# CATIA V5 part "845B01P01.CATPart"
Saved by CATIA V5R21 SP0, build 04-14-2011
Part number: 845B01P21
Bounding box of the stored display mesh (mm): x -76.5 to 76.5, y -25.54 to 25.54, z -6.5 to 6.5
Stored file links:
  C:\Users\ALI OZGUN\Desktop\alhan\845B01P01.CATPart
  Copy (1) of 845B01P21.CATPart
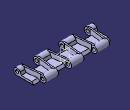
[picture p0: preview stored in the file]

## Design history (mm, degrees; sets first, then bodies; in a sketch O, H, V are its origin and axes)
Body1 (main body)
  Sketch1 on yz-plane, origin (0, 0, 0), H (0, 1, 0), V (0, 0, 1)
    construction line L1 (-19.05, 0) -> (19.05, 0)
    point P1 (-19.05, 0)
    point P2 (19.05, 0)
    line L2 (-19.05, 6.5) -> (19.05, 6.5)
    line L3 (19.05, -6.5) -> (-19.05, -6.5)
    arc A1 centre (19.05, 0) radius 6.5 from (19.05, 6.5) to (19.05, -6.5) cw
    arc A2 centre (-19.05, 0) radius 6.5 from (-19.05, -6.5) to (-19.05, 6.5) cw
    circle A3 centre (19.05, 0) radius 3.25
    circle A4 centre (-19.05, 0) radius 3.25
    distance L1 L2 = 6.5
    length L1 = 38.1
    distance P2 V = 19.05
    radius A3 = 3.25
    radius A4 = 3.25
    coincidence: P1 H
    horizontal: L1 H
    tangency: A1 L2, A2 L2, A1 L3, A2 L3
  Pad1: profile Sketch1, direction (1, 0, 0), length 76.5, mirrored extent
  Sketch2 on face of Pad1 from Sketch1.L2, origin (0, 0, 6.5), H (1, 0, 0), V (0, 1, 0)
    line L1 (38, -14) -> (64, -14)
    line L2 (64, -14) -> (64, -36.0786)
    line L3 (64, -36.0786) -> (38, -36.0786)
    line L4 (38, -36.0786) -> (38, -14)
    line L5 (-13, -14) -> (13, -14)
    line L6 (13, -14) -> (13, -36.0786)
    line L7 (13, -36.0786) -> (-13, -36.0786)
    line L8 (-13, -36.0786) -> (-13, -14)
    point P7 (13, -36.0786)
    line L9 (-64, -14) -> (-38, -14)
    line L10 (-38, -14) -> (-38, -32.269)
    line L11 (-38, -32.269) -> (-64, -32.269)
    line L12 (-64, -32.269) -> (-64, -14)
    line L13 (85.7823, 31.3847) -> (63.5, 31.3847)
    line L14 (63.5, 31.3847) -> (63.5, 14)
    line L15 (63.5, 14) -> (85.7823, 14)
    line L16 (85.7823, 14) -> (85.7823, 31.3847)
    point P17 (12.5, 31.3847)
    line L17 (12.5, 31.3847) -> (38.5, 31.3847)
    line L18 (38.5, 31.3847) -> (38.5, 14)
    line L19 (38.5, 14) -> (12.5, 14)
    line L20 (12.5, 14) -> (12.5, 31.3847)
    point P19 (38.5, 14)
    line L21 (-38.5, 32.0801) -> (-12.5, 32.0801)
    line L22 (-12.5, 32.0801) -> (-12.5, 14)
    line L23 (-12.5, 14) -> (-38.5, 14)
    line L24 (-38.5, 14) -> (-38.5, 32.0801)
    point P23 (-12.5, 14)
    line L25 (-81.4786, 33.8185) -> (-63.5, 33.8185)
    line L26 (-63.5, 33.8185) -> (-63.5, 14)
    line L27 (-63.5, 14) -> (-81.4786, 14)
    line L28 (-81.4786, 14) -> (-81.4786, 33.8185)
    point P27 (-63.5, 14)
    reference projected line E1 (76.5, 19.05) -> (76.5, -19.05) from edge [face of Pad1 from Sketch1.L2 | end face of Pad1]
    reference projected line E2 (-76.5, 19.05) -> (-76.5, -19.05) from edge [start face of Pad1 | face of Pad1 from Sketch1.L2]
    reference projected line E3 (-76.5, 19.05) -> (-76.5, -19.05) from edge [start face of Pad1 | face of Pad1 from Sketch1.L2]
    reference projected line E4 (76.5, 19.05) -> (76.5, -19.05) from edge [face of Pad1 from Sketch1.L2 | end face of Pad1]
    distance L14 E1 = 13
    distance L26 E2 = 13
    distance L12 E3 = 12.5
    distance L2 E4 = 12.5
    distance L23 L5 = 28
    distance L5 H = 14
    distance L4 L2 = 26
    distance L12 L10 = 26
    distance L10 L8 = 25
    distance L6 L4 = 25
    distance L24 L26 = 25
    distance L18 L14 = 25
    distance L26 L22 = 51
    distance L20 L18 = 26
    horizontal: L1 H, L3 H, L5 H, L7 H, L9 H, L11 H, L13 H, L15 H, L17 H, L19 H, L21 H, L23 H, L25 H, L27 H
    vertical: L2 V, L4 V, L6 V, L8 V, L10 V, L12 V, L14 V, L16 V, L18 V, L20 V, L22 V, L24 V, L26 V, L28 V
    coincidence: P7 L3, P17 L13, P19 L15, P23 L15, P27 L15, L1 L5, L9 L5
  Pocket1: profile Sketch2, direction (0, 0, -1), length 53.5
  Sketch3 on end face of Pad1, origin (76.5, 0, 0), H (0, 1, 0), V (0, 0, 1)
    projected arc E1 centre (19.05, 0) radius 6.5 from (19.05, -6.5) to (19.05, 6.5) ccw from edge [face of Pocket1 from Sketch2.L14 | face of Pad1 from Sketch1.A1]
    projected arc E2 centre (19.05, 0) radius 6.5 from (19.05, -6.5) to (13.0358, 2.4657) ccw from edge [face of Pocket1 from Sketch2.L14 | face of Pad1 from Sketch1.A1]
    point P1 (19.05, -6.5)
    projected arc E3 centre (-19.05, 0) radius 6.5 from (-19.05, 6.5) to (-19.05, -6.5) ccw from edge [face of Pad1 from Sketch1.A2 | end face of Pad1]
    projected arc E4 centre (-19.05, 0) radius 6.5 from (-13.0358, 2.4657) to (-19.05, -6.5) ccw from edge [face of Pad1 from Sketch1.A2 | end face of Pad1]
    point P4 (-19.05, -6.5)
    projected line E5 (-19.05, -6.5) -> (14, -6.5) from edge [face of Pad1 from Sketch1.L3 | end face of Pad1]
    point P5 (-19.05, -6.5)
    projected line E6 (19.05, -6.5) -> (14, -6.5) from edge [face of Pocket1 from Sketch2.L14 | face of Pad1 from Sketch1.L3]
    point P7 (19.05, -6.5)
    line L1 (-13.0358, 2.4657) -> (-11, -2.5)
    line L2 (-11, -2.5) -> (11, -2.5)
    point P10 (11, -2.5)
    line L3 (11, -2.5) -> (13.0358, 2.4657)
    distance L2 E5 = 4
    length L2 = 22
    distance P10 V = 11
    horizontal: L2 H
    tangency: L3 E1, L1 E3
    coincidence: P1 P7, P4 P5
  Pocket2: profile Sketch3, direction (-1, 0, 0), length 172.5, outer side
  Sketch4 on face of Pocket2 from Sketch3.L2, origin (0, 0, -2.5), H (1, 0, 0), V (0, 1, 0)
    projected line E1 (38, -14) -> (38, -25.55) from edge [face of Pocket2 | face of Pocket1 from Sketch2.L4]
    projected line E2 (38, -14) -> (38, -19.05) from edge [face of Pocket2 | face of Pocket1 from Sketch2.L4]
    point P1 (38, -14)
    point P2 (38, -25.55)
    projected line E3 (13, -25.55) -> (13, -14) from edge [face of Pocket2 | face of Pocket1 from Sketch2.L6]
    projected line E4 (13, -19.05) -> (13, -14) from edge [face of Pocket2 | face of Pocket1 from Sketch2.L6]
    point P3 (13, -25.55)
    point P4 (13, -14)
    projected line E5 (64, -25.55) -> (64, -14) from edge [face of Pocket2 | face of Pocket1 from Sketch2.L2]
    projected line E6 (64, -19.05) -> (64, -14) from edge [face of Pocket2 | face of Pocket1 from Sketch2.L2]
    point P5 (64, -25.55)
    point P6 (64, -14)
    projected line E7 (38.5, 14) -> (38.5, 25.55) from edge [face of Pocket2 | face of Pocket1 from Sketch2.L18]
    projected line E8 (38.5, 14) -> (38.5, 19.05) from edge [face of Pocket2 | face of Pocket1 from Sketch2.L18]
    point P7 (38.5, 14)
    point P8 (38.5, 25.55)
    projected line E9 (63.5, 14) -> (63.5, 25.55) from edge [face of Pocket1 from Sketch2.L14 | face of Pocket2]
    projected line E10 (63.5, 14) -> (63.5, 19.05) from edge [face of Pocket1 from Sketch2.L14 | face of Pocket2]
    point P9 (63.5, 14)
    point P10 (63.5, 25.55)
    projected line E11 (12.5, 25.55) -> (12.5, 14) from edge [face of Pocket2 | face of Pocket1 from Sketch2.L20]
    projected line E12 (12.5, 19.05) -> (12.5, 14) from edge [face of Pocket2 | face of Pocket1 from Sketch2.L20]
    point P11 (12.5, 25.55)
    point P12 (12.5, 14)
    offset line E13 (9.5, 25.55) -> (9.5, 14) from edge [face of Pocket2 | face of Pocket1 from Sketch2.L20]
    offset line E14 (9.5, 19.05) -> (9.5, 14) from edge [face of Pocket2 | face of Pocket1 from Sketch2.L20]
    point P13 (9.5, 25.55)
    point P14 (9.5, 14)
    offset line E15 (16, -25.55) -> (16, -14) from edge [face of Pocket2 | face of Pocket1 from Sketch2.L6]
    offset line E16 (16, -19.05) -> (16, -14) from edge [face of Pocket2 | face of Pocket1 from Sketch2.L6]
    point P15 (16, -25.55)
    point P16 (16, -14)
    offset line E17 (35, -14) -> (35, -25.55) from edge [face of Pocket2 | face of Pocket1 from Sketch2.L4]
    offset line E18 (35, -14) -> (35, -19.05) from edge [face of Pocket2 | face of Pocket1 from Sketch2.L4]
    point P17 (35, -14)
    point P18 (35, -25.55)
    offset line E19 (41.5, 14) -> (41.5, 25.55) from edge [face of Pocket2 | face of Pocket1 from Sketch2.L18]
    offset line E20 (41.5, 14) -> (41.5, 19.05) from edge [face of Pocket2 | face of Pocket1 from Sketch2.L18]
    point P19 (41.5, 14)
    point P20 (41.5, 25.55)
    offset line E21 (60.5, 14) -> (60.5, 25.55) from edge [face of Pocket1 from Sketch2.L14 | face of Pocket2]
    offset line E22 (60.5, 14) -> (60.5, 19.05) from edge [face of Pocket1 from Sketch2.L14 | face of Pocket2]
    point P21 (60.5, 14)
    point P22 (60.5, 25.55)
    offset line E23 (67, -25.55) -> (67, -14) from edge [face of Pocket2 | face of Pocket1 from Sketch2.L2]
    offset line E24 (67, -19.05) -> (67, -14) from edge [face of Pocket2 | face of Pocket1 from Sketch2.L2]
    point P23 (67, -25.55)
    point P24 (67, -14)
    line L1 (13, -14) -> (9.5, 14)
    line L2 (16, -14) -> (12.5, 14)
    line L3 (35, -14) -> (38.5, 14)
    line L4 (38, -14) -> (41.5, 14)
    line L5 (64, -14) -> (60.5, 14)
    line L6 (67, -14) -> (63.5, 14)
    projected line E25 through (0, -19.05) direction (1, 0) from axis of face of Pocket2
    projected line E26 (13, -19.05) -> (16, -19.05) from axis of face of Pocket2
    projected line E27 (64, -19.05) -> (67, -19.05) from axis of face of Pocket2
    projected line E28 (35, -19.05) -> (38, -19.05) from axis of face of Pocket2
    point P25 (-10000000, -19.05)
    point P26 (10000000, -19.05)
    point P27 (67, -19.05)
    point P28 (38, -19.05)
    point P29 (64, -19.05)
    point P30 (64, -19.05)
    point P31 (38, -19.05)
    point P32 (35, -19.05)
    point P33 (16, -19.05)
    point P34 (35, -19.05)
    point P35 (16, -19.05)
    point P36 (13, -19.05)
    point P37 (13, -19.05)
    projected line E29 through (0, 19.05) direction (1, 0) from axis of face of Pocket2
    projected line E30 (9.5, 19.05) -> (12.5, 19.05) from axis of face of Pocket2
    projected line E31 (38.5, 19.05) -> (41.5, 19.05) from axis of face of Pocket2
    projected line E32 (60.5, 19.05) -> (63.5, 19.05) from axis of face of Pocket2
    point P38 (-10000000, 19.05)
    point P39 (10000000, 19.05)
    point P40 (63.5, 19.05)
    point P41 (9.5, 19.05)
    point P42 (9.5, 19.05)
    point P43 (12.5, 19.05)
    point P44 (12.5, 19.05)
    point P45 (38.5, 19.05)
    point P46 (38.5, 19.05)
    point P47 (41.5, 19.05)
    point P48 (60.5, 19.05)
    point P49 (41.5, 19.05)
    point P50 (60.5, 19.05)
    point P51 (-10000000, -19.05)
    point P52 (10000000, -19.05)
    point P53 (-10000000, 19.05)
    point P54 (10000000, 19.05)
    construction line L7 through (0, -19.05) direction (-1, 0)
    construction line L8 through (0, 19.05) direction (-1, 0)
    point P55 (-10000000, -19.05)
    point P56 (10000000, -19.05)
    point P57 (-16, -19.05)
    point P58 (-13, -19.05)
    point P59 (-67, -19.05)
    point P60 (-64, -19.05)
    point P61 (-38, -19.05)
    point P62 (-35, -19.05)
    point P63 (-38, -25.55)
    point P64 (-38, -14)
    point P65 (-38, -19.05)
    point P66 (-13, -14)
    point P67 (-13, -25.55)
    point P68 (-13, -19.05)
    point P69 (-64, -14)
    point P70 (-64, -25.55)
    point P71 (-64, -19.05)
    point P72 (-38.5, 25.55)
    point P73 (-38.5, 14)
    point P74 (-38.5, 19.05)
    point P75 (-63.5, 25.55)
    point P76 (-63.5, 14)
    point P77 (-63.5, 19.05)
    point P78 (-12.5, 14)
    point P79 (-12.5, 25.55)
    point P80 (-12.5, 19.05)
    point P81 (-9.5, 14)
    point P82 (-9.5, 25.55)
    point P83 (-9.5, 19.05)
    point P84 (-16, -14)
    point P85 (-16, -25.55)
    point P86 (-16, -19.05)
    point P87 (-35, -25.55)
    point P88 (-35, -14)
    point P89 (-35, -19.05)
    point P90 (-41.5, 25.55)
    point P91 (-41.5, 14)
    point P92 (-41.5, 19.05)
    point P93 (-60.5, 25.55)
    point P94 (-60.5, 14)
    point P95 (-60.5, 19.05)
    point P96 (-67, -14)
    point P97 (-67, -25.55)
    line L9 (-13, -14) -> (-9.5, 14)
    line L10 (-16, -14) -> (-12.5, 14)
    line L11 (-35, -14) -> (-38.5, 14)
    line L12 (-38, -14) -> (-41.5, 14)
    line L13 (-64, -14) -> (-60.5, 14)
    line L14 (-67, -14) -> (-63.5, 14)
    point P98 (-10000000, 19.05)
    point P99 (10000000, 19.05)
    point P100 (-12.5, 19.05)
    point P101 (-9.5, 19.05)
    point P102 (-41.5, 19.05)
    point P103 (-38.5, 19.05)
    point P104 (-60.5, 19.05)
    construction line L15 through (0, -19.05) direction (-1, 0)
    line L16 (-13, -19.05) -> (-16, -19.05)
    line L17 (-64, -19.05) -> (-67, -19.05)
    line L18 (-35, -19.05) -> (-38, -19.05)
    construction line L19 (-38, -14) -> (-38, -25.55)
    line L20 (-38, -14) -> (-38, -19.05)
    construction line L21 (-13, -25.55) -> (-13, -14)
    line L22 (-13, -19.05) -> (-13, -14)
    construction line L23 (-64, -25.55) -> (-64, -14)
    line L24 (-64, -19.05) -> (-64, -14)
    construction line L25 (-38.5, 14) -> (-38.5, 25.55)
    line L26 (-38.5, 14) -> (-38.5, 19.05)
    construction line L27 (-63.5, 14) -> (-63.5, 25.55)
    line L28 (-63.5, 14) -> (-63.5, 19.05)
    construction line L29 (-12.5, 25.55) -> (-12.5, 14)
    line L30 (-12.5, 19.05) -> (-12.5, 14)
    construction line L31 (-9.5, 25.55) -> (-9.5, 14)
    line L32 (-9.5, 19.05) -> (-9.5, 14)
    construction line L33 (-16, -25.55) -> (-16, -14)
    line L34 (-16, -19.05) -> (-16, -14)
    construction line L35 (-35, -14) -> (-35, -25.55)
    line L36 (-35, -14) -> (-35, -19.05)
    construction line L37 (-41.5, 14) -> (-41.5, 25.55)
    line L38 (-41.5, 14) -> (-41.5, 19.05)
    construction line L39 (-60.5, 14) -> (-60.5, 25.55)
    line L40 (-60.5, 14) -> (-60.5, 19.05)
    construction line L41 (-67, -25.55) -> (-67, -14)
    line L42 (-67, -19.05) -> (-67, -14)
    construction line L43 through (0, 19.05) direction (-1, 0)
    line L44 (-9.5, 19.05) -> (-12.5, 19.05)
    line L45 (-38.5, 19.05) -> (-41.5, 19.05)
    line L46 (-60.5, 19.05) -> (-63.5, 19.05)
    parallelism: L2 L1, L4 L3
    coincidence: E1 P28, E5 P29, E25 P30, E25 P31, E25 P32, E15 P33, E17 P34, E25 P35, E25 P36, E3 P37, E13 P41, E29 P42, E29 P43, E11 P44, E7 P45, E29 P46, E29 P47, E29 P48, E19 P49, E21 P50, P28 P31, P29 P30, P32 P34, P33 P35, P36 P37, P41 P42, P43 P44, P45 P46, P47 P49, P48 P50
    symmetry: P26 P51 V, P25 P52 V, E25 L7 V, P39 P53 V, P38 P54 V, E29 L8 V, P26 P55 V, P25 P56 V, P33 P57 V, P37 P58 V, P27 P59 V, P29 P60 V, P28 P61 V, P34 P62 V, E25 L15 V, P2 P63 V, P1 P64 V, P31 P65 V, E1 L19 V, P4 P66 V, P3 P67 V, P36 P68 V, E3 L21 V, P6 P69 V, P5 P70 V, P30 P71 V, E5 L23 V, P8 P72 V, P7 P73 V, P46 P74 V, E7 L25 V, P10 P75 V, P9 P76 V, P40 P77 V, E9 L27 V, P12 P78 V, P11 P79 V, P43 P80 V, E11 L29 V, P14 P81 V, P13 P82 V, P42 P83 V, E13 L31 V, P16 P84 V, P15 P85 V, P35 P86 V, E15 L33 V, P18 P87 V, P17 P88 V, P32 P89 V, E17 L35 V, P20 P90 V, P19 P91 V, P47 P92 V, E19 L37 V, P22 P93 V, P21 P94 V, P48 P95 V, E21 L39 V, P24 P96 V, P23 P97 V, E23 L41 V, L1 L9 V, L2 L10 V, L3 L11 V, L4 L12 V, L5 L13 V, L6 L14 V, P39 P98 V, P38 P99 V, P44 P100 V, P41 P101 V, P49 P102 V, P45 P103 V, P50 P104 V, E29 L43 V, E25 L18 V, E25 L17 V, E25 L16 V, E1 L20 V, E3 L22 V, E5 L24 V, E7 L26 V, E9 L28 V, E11 L30 V, E13 L32 V, E15 L34 V, E17 L36 V, E19 L38 V, E21 L40 V, E23 L42 V, E29 L46 V, E29 L45 V, E29 L44 V
  Pad2: profile Sketch4, direction (0, 0, 1), length 9
  Sketch5 on yz-plane, origin (0, 0, 0), H (0, 1, 0), V (0, 0, 1)
    projected circle E1 centre (-19.05, 0) radius 3.25 from edge [end face of Pad1 | face of Pad1 from Sketch1.A4]
    circle A1 centre (19.05, 0) radius 3.25
    reference projected circle E2 centre (19.05, 0) radius 3.25 from edge [face of Pad1 from Sketch1.A3 | face of Pad2]
    coincidence: A1 E2
  Pocket3: profile Sketch5, direction (-1, 0, 0), length 95, mirrored extent
  RemoveFace1: RemoveFaces (face of Pocket2 from Sketch3.L3; face of Pocket2; face of Pocket2 from Sketch3.L3; face of Pocket2; face of Pocket2 from Sketch3.L1; face of Pocket2; face of Pocket2 from Sketch3.L1; face of Pocket2; face of Pocket2; face of Pocket2; face of Pocket2; face of Pocket2 from Sketch3.L3; face of Pocket2 from Sketch3.L3; face of Pocket2 from Sketch3.L1)
  Chamfer1: length 4, angle 45, on edge [face of Pocket1 from Sketch2.L27 | face of Pocket2 from Sketch3.L2]; edge [face of Pocket1 from Sketch2.L9 | face of Pocket2 from Sketch3.L2]; edge [face of Pocket1 from Sketch2.L19 | face of Pocket2 from Sketch3.L2]; edge [face of Pocket1 from Sketch2.L5 | face of Pocket2 from Sketch3.L2]; edge [face of Pocket1 from Sketch2.L1 | face of Pocket2 from Sketch3.L2]; edge [face of Pocket1 from Sketch2.L15 | face of Pocket2 from Sketch3.L2]; edge [face of Pocket1 from Sketch2.L23 | face of Pocket2 from Sketch3.L2]
Body2
  Solid1: linked copy from another document
  Translate1: Direction zx-plane, ToTransfor Solid1, Length 38.1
